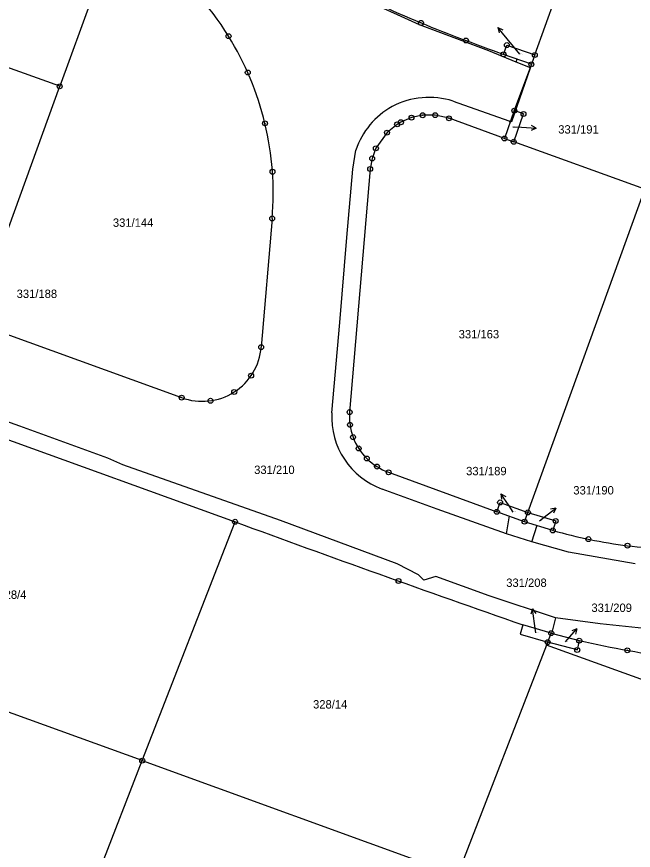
# Model space of a CAD drawing. Extents: x -770973 to -770265, y -1049936 to -1049427.
# Drawn here: x -770637.6 to -770575, y -1049731.9 to -1049647.3 of the extents above; entities that cross this region are included whole.
import ezdxf

# ---------------------------------------------------------------- set-up
doc = ezdxf.new("R2010")
doc.units = 0
for name, color, linetype in [('Vrstva 1', 7, 'Continuous'), ('Vrstva 13', 7, 'Continuous'), ('Vrstva 14', 7, 'Continuous'), ('Vrstva 16', 7, 'Continuous'), ('Vrstva 28', 7, 'Continuous'), ('Vrstva 50', 7, 'Continuous')]:
    doc.layers.add(name, color=color, linetype=linetype)

msp = doc.modelspace()

# ---------------------------------------------------------------- linework, layer by layer
at = {"layer": 'Vrstva 1'}
for p, q in [((-770584.98, -1049651.2), (-770577.41, -1049630.29)), ((-770627.29, -1049638.1), (-770633.21, -1049654.38)), ((-770633.21, -1049654.38), (-770663.4, -1049643.45)), ((-770588.15, -1049651.14), (-770587.82, -1049650.2)), ((-770587.82, -1049650.2), (-770584.98, -1049651.2)), ((-770585.33, -1049652.15), (-770588.15, -1049651.14)), ((-770584.98, -1049651.2), (-770585.33, -1049652.15)), ((-770585.33, -1049652.15), (-770587.06, -1049656.85)), ((-770641.55, -1049677.41), (-770633.21, -1049654.38)), ((-770587.06, -1049656.85), (-770588.06, -1049659.68)), ((-770587.12, -1049660.01), (-770586.12, -1049657.19)), ((-770586.12, -1049657.19), (-770587.06, -1049656.85)), ((-770598.57, -1049658.03), (-770598.96, -1049658.24)), ((-770597.5, -1049657.56), (-770598.57, -1049658.03)), ((-770596.36, -1049657.32), (-770597.5, -1049657.56)), ((-770595.1, -1049657.31), (-770596.36, -1049657.32)), ((-770593.69, -1049657.63), (-770595.1, -1049657.31)), ((-770588.06, -1049659.68), (-770593.69, -1049657.63)), ((-770598.96, -1049658.24), (-770599.98, -1049659.08)), ((-770599.98, -1049659.08), (-770601.11, -1049660.67)), ((-770588.06, -1049659.68), (-770587.12, -1049660.01)), ((-770601.11, -1049660.67), (-770601.49, -1049661.7)), ((-770573.81, -1049664.83), (-770587.12, -1049660.01)), ((-770601.49, -1049661.7), (-770601.69, -1049662.77)), ((-770601.69, -1049662.77), (-770603.78, -1049687.44)), ((-770585.68, -1049697.62), (-770573.81, -1049664.83)), ((-770611.64, -1049667.79), (-770612.76, -1049680.85)), ((-770639.05, -1049679.38), (-770620.83, -1049685.97)), ((-770644.61, -1049688), (-770615.41, -1049698.57)), ((-770599.82, -1049693.55), (-770588.83, -1049697.56)), ((-770588.83, -1049697.56), (-770588.5, -1049696.61)), ((-770588.5, -1049696.61), (-770585.68, -1049697.62)), ((-770586.02, -1049698.56), (-770588.83, -1049697.56)), ((-770586.02, -1049698.56), (-770585.68, -1049697.62)), ((-770585.68, -1049697.62), (-770582.86, -1049698.49)), ((-770624.83, -1049722.81), (-770615.41, -1049698.57)), ((-770583.15, -1049699.45), (-770586.02, -1049698.56)), ((-770582.86, -1049698.49), (-770583.15, -1049699.45)), ((-770586.18, -1049709.03), (-770586.46, -1049709.99)), ((-770583.31, -1049709.87), (-770586.18, -1049709.03)), ((-770586.46, -1049709.99), (-770583.67, -1049710.78)), ((-770583.67, -1049710.78), (-770583.31, -1049709.87)), ((-770583.31, -1049709.87), (-770580.47, -1049710.63)), ((-770624.83, -1049722.81), (-770656.82, -1049711.23)), ((-770583.79, -1049711.08), (-770592.84, -1049734.39)), ((-770583.79, -1049711.08), (-770583.67, -1049710.78)), ((-770552.69, -1049722.34), (-770583.79, -1049711.08)), ((-770580.67, -1049711.58), (-770583.67, -1049710.78)), ((-770580.47, -1049710.63), (-770580.67, -1049711.58)), ((-770633.88, -1049746.11), (-770624.83, -1049722.81)), ((-770624.83, -1049722.81), (-770592.84, -1049734.39))]:
    msp.add_line(p, q, dxfattribs=at)
for centre, radius, start, end in [((-770641.671, -1049665.124), 30.101, 31.7359, 52.91598), ((-770563.212, -1049566.923), 87.609, 241.27361, 247.64799), ((-770506.43, -1049423.863), 241.523, 248.09613, 250.22338), ((-770641.784, -1049665.239), 30.258, 13.56856, 31.809), ((-770641.923, -1049665.228), 30.391, 355.16466, 13.48744), ((-770618.706, -1049680.376), 5.965, 302.62625, 355.44623), ((-770618.732, -1049680.33), 6.018, 249.591, 302.59454), ((-770597.707, -1049687.897), 6.09, 175.69338, 199.99797), ((-770597.943, -1049687.977), 5.841, 200.05783, 225.59925), ((-770597.728, -1049687.803), 6.116, 225.2978, 249.99497), ((-770023.191, -1048089.712), 1714.394, 249.791394, 250.82895), ((-770568.602, -1049647.614), 53.839, 254.32281, 262.56352), ((-770568.043, -1049639.768), 61.693, 262.99237, 270.30037), ((-770552.252, -1049582.755), 130.951, 257.55595, 262.02506)]:
    msp.add_arc(centre, radius, start, end, dxfattribs=at)
at = {"layer": 'Vrstva 13'}
for p, q in [((-770586.5, -1049651.12), (-770587.77, -1049649.57)), ((-770587.21, -1049658.48), (-770586.34, -1049658.54)), ((-770587.16, -1049697.59), (-770587.58, -1049696.96)), ((-770584.51, -1049698.49), (-770584.03, -1049698.11)), ((-770584.88, -1049709.84), (-770585.01, -1049708.9)), ((-770581.86, -1049710.76), (-770581.68, -1049710.55))]:
    msp.add_line(p, q, dxfattribs=at)
at = {"layer": 'Vrstva 16'}
for p, q in [((-770587.77, -1049649.57), (-770588.72, -1049648.41)), ((-770588.72, -1049648.41), (-770588.6, -1049648.95)), ((-770588.72, -1049648.41), (-770588.21, -1049648.64)), ((-770586.34, -1049658.54), (-770584.84, -1049658.63)), ((-770584.84, -1049658.63), (-770585.36, -1049658.85)), ((-770584.84, -1049658.63), (-770585.33, -1049658.35)), ((-770587.58, -1049696.96), (-770588.42, -1049695.72)), ((-770588.42, -1049695.72), (-770588.35, -1049696.27)), ((-770588.42, -1049695.72), (-770587.93, -1049695.99)), ((-770584.03, -1049698.11), (-770582.85, -1049697.19)), ((-770582.85, -1049697.19), (-770583.4, -1049697.3)), ((-770582.85, -1049697.19), (-770583.09, -1049697.69)), ((-770585.21, -1049707.41), (-770585.39, -1049707.94)), ((-770585.01, -1049708.9), (-770585.21, -1049707.41)), ((-770585.21, -1049707.41), (-770584.89, -1049707.88)), ((-770581.68, -1049710.55), (-770580.7, -1049709.42)), ((-770580.7, -1049709.42), (-770581.21, -1049709.63)), ((-770580.7, -1049709.42), (-770580.84, -1049709.96))]:
    msp.add_line(p, q, dxfattribs=at)
at = {"layer": 'Vrstva 28'}
for centre, radius in [((-770596.53, -1049647.95), 0.25), ((-770596.53, -1049647.95), 0.005), ((-770616.07, -1049649.29), 0.25), ((-770616.07, -1049649.29), 0.005), ((-770591.97, -1049649.73), 0.25), ((-770591.97, -1049649.73), 0.005), ((-770587.82, -1049650.2), 0.25), ((-770587.82, -1049650.2), 0.005), ((-770588.15, -1049651.14), 0.25), ((-770588.15, -1049651.14), 0.005), ((-770584.98, -1049651.2), 0.25), ((-770584.98, -1049651.2), 0.005), ((-770585.33, -1049652.15), 0.25), ((-770585.33, -1049652.15), 0.005), ((-770614.12, -1049652.98), 0.25), ((-770614.12, -1049652.98), 0.005), ((-770633.21, -1049654.38), 0.25), ((-770633.21, -1049654.38), 0.005), ((-770596.36, -1049657.32), 0.25), ((-770595.1, -1049657.31), 0.25), ((-770587.06, -1049656.85), 0.25), ((-770587.06, -1049656.85), 0.005), ((-770586.12, -1049657.19), 0.25), ((-770586.12, -1049657.19), 0.005), ((-770612.37, -1049658.14), 0.25), ((-770612.37, -1049658.14), 0.005), ((-770598.96, -1049658.24), 0.25), ((-770598.57, -1049658.03), 0.25), ((-770598.57, -1049658.03), 0.005), ((-770597.5, -1049657.56), 0.25), ((-770597.5, -1049657.56), 0.005), ((-770596.36, -1049657.32), 0.005), ((-770595.1, -1049657.31), 0.005), ((-770593.69, -1049657.63), 0.25), ((-770593.69, -1049657.63), 0.005), ((-770599.98, -1049659.08), 0.25), ((-770598.96, -1049658.24), 0.005), ((-770599.98, -1049659.08), 0.005), ((-770588.06, -1049659.68), 0.25), ((-770588.06, -1049659.68), 0.005), ((-770587.12, -1049660.01), 0.25), ((-770601.11, -1049660.67), 0.25), ((-770601.11, -1049660.67), 0.005), ((-770587.12, -1049660.01), 0.005), ((-770601.49, -1049661.7), 0.25), ((-770601.49, -1049661.7), 0.005), ((-770611.61, -1049663.05), 0.25), ((-770611.61, -1049663.05), 0.005), ((-770601.69, -1049662.77), 0.25), ((-770601.69, -1049662.77), 0.005), ((-770611.64, -1049667.79), 0.25), ((-770611.64, -1049667.79), 0.005), ((-770612.76, -1049680.85), 0.25), ((-770612.76, -1049680.85), 0.005), ((-770613.78, -1049683.74), 0.25), ((-770613.78, -1049683.74), 0.005), ((-770615.49, -1049685.4), 0.25), ((-770620.83, -1049685.97), 0.25), ((-770620.83, -1049685.97), 0.005), ((-770617.9, -1049686.29), 0.25), ((-770615.49, -1049685.4), 0.005), ((-770617.9, -1049686.29), 0.005), ((-770603.78, -1049687.44), 0.25), ((-770603.78, -1049687.44), 0.005), ((-770603.74, -1049688.73), 0.25), ((-770603.74, -1049688.73), 0.005), ((-770603.43, -1049689.98), 0.25), ((-770603.43, -1049689.98), 0.005), ((-770602.86, -1049691.13), 0.25), ((-770602.86, -1049691.13), 0.005), ((-770602.03, -1049692.15), 0.25), ((-770602.03, -1049692.15), 0.005), ((-770601, -1049692.97), 0.25), ((-770601, -1049692.97), 0.005), ((-770599.82, -1049693.55), 0.25), ((-770599.82, -1049693.55), 0.005), ((-770588.5, -1049696.61), 0.25), ((-770588.5, -1049696.61), 0.005), ((-770588.83, -1049697.56), 0.25), ((-770588.83, -1049697.56), 0.005), ((-770585.68, -1049697.62), 0.25), ((-770585.68, -1049697.62), 0.005), ((-770615.41, -1049698.57), 0.25), ((-770615.41, -1049698.57), 0.005), ((-770586.02, -1049698.56), 0.25), ((-770586.02, -1049698.56), 0.005), ((-770582.86, -1049698.49), 0.25), ((-770582.86, -1049698.49), 0.005), ((-770583.15, -1049699.45), 0.25), ((-770583.15, -1049699.45), 0.005), ((-770579.54, -1049700.33), 0.25), ((-770579.54, -1049700.33), 0.005), ((-770575.57, -1049701), 0.25), ((-770575.57, -1049701), 0.005), ((-770598.82, -1049704.58), 0.25), ((-770598.82, -1049704.58), 0.005), ((-770583.31, -1049709.87), 0.25), ((-770583.67, -1049710.78), 0.25), ((-770583.31, -1049709.87), 0.005), ((-770580.47, -1049710.63), 0.25), ((-770583.67, -1049710.78), 0.005), ((-770580.67, -1049711.58), 0.25), ((-770580.47, -1049710.63), 0.005), ((-770575.59, -1049711.61), 0.25), ((-770580.67, -1049711.58), 0.005), ((-770575.59, -1049711.61), 0.005), ((-770624.83, -1049722.81), 0.25), ((-770624.83, -1049722.81), 0.005)]:
    msp.add_circle(centre, radius, dxfattribs=at)
at = {"layer": 'Vrstva 50'}
for p, q in [((-770596.69, -1049648.13), (-770601.84, -1049645.81)), ((-770589.65, -1049650.78), (-770596.69, -1049648.13)), ((-770586.88, -1049651.93), (-770589.65, -1049650.78)), ((-770586.88, -1049651.93), (-770586.77, -1049651.61)), ((-770585.4, -1049652.5), (-770586.88, -1049651.93)), ((-770587.31, -1049657.96), (-770585.4, -1049652.5)), ((-770593.27, -1049655.88), (-770587.62, -1049657.89)), ((-770587.62, -1049657.89), (-770587.48, -1049658.07)), ((-770587.62, -1049657.89), (-770587.31, -1049657.96)), ((-770603.46, -1049662.78), (-770603.14, -1049660.85)), ((-770604.05, -1049669.71), (-770603.46, -1049662.78)), ((-770604.78, -1049678.35), (-770604.05, -1049669.71)), ((-770605.59, -1049687.53), (-770604.78, -1049678.35)), ((-770637.26, -1049688.86), (-770644.63, -1049686.31)), ((-770628.31, -1049692.12), (-770637.26, -1049688.86)), ((-770626.79, -1049692.8), (-770628.31, -1049692.12)), ((-770610.79, -1049698.43), (-770626.79, -1049692.8)), ((-770594.88, -1049697.28), (-770600.49, -1049695.25)), ((-770587.84, -1049699.78), (-770594.88, -1049697.28)), ((-770598.94, -1049702.83), (-770610.79, -1049698.43)), ((-770587.84, -1049699.78), (-770587.55, -1049697.96)), ((-770585.29, -1049700.62), (-770584.74, -1049698.9)), ((-770585.29, -1049700.62), (-770587.84, -1049699.78)), ((-770581.57, -1049701.66), (-770585.29, -1049700.62)), ((-770574.78, -1049702.84), (-770581.57, -1049701.66)), ((-770596.79, -1049703.95), (-770598.94, -1049702.83)), ((-770596.24, -1049704.51), (-770596.79, -1049703.95)), ((-770595.03, -1049704.14), (-770596.24, -1049704.51)), ((-770589.6, -1049706.07), (-770595.03, -1049704.14)), ((-770582.89, -1049708.33), (-770589.6, -1049706.07)), ((-770582.89, -1049708.33), (-770583.25, -1049709.79)), ((-770578.34, -1049708.92), (-770582.89, -1049708.33)), ((-770573.85, -1049709.39), (-770578.34, -1049708.92))]:
    msp.add_line(p, q, dxfattribs=at)
for centre, radius, start, end in [((-770595.701, -1049663.565), 8.061, 72.4461, 117.87609), ((-770595.652, -1049663.349), 7.894, 118.924, 161.54158), ((-770597.801, -1049687.929), 7.799, 177.06892, 249.83032)]:
    msp.add_arc(centre, radius, start, end, dxfattribs=at)

# ---------------------------------------------------------------- texts
at = {"layer": 'Vrstva 14'}
for s, height, p in [('331/192', 0.05, (-770586.5, -1049651.12)), ('331/191', 0.05, (-770587.21, -1049658.48)), ('331/144', 0.85, (-770627.81, -1049668.64)), ('331/163', 0.85, (-770592.71, -1049679.96)), ('331/210', 0.85, (-770613.47, -1049693.72)), ('331/189', 0.05, (-770587.16, -1049697.59)), ('331/190', 0.05, (-770584.51, -1049698.49)), ('328/4', 0.85, (-770639.43, -1049706.39)), ('331/208', 0.05, (-770584.88, -1049709.84)), ('331/209', 0.05, (-770581.86, -1049710.76)), ('328/14', 0.85, (-770607.49, -1049717.52))]:
    msp.add_text(s, height=height, dxfattribs=at).set_placement(p)
at = {"layer": 'Vrstva 16'}
for s, p in [('331/191', (-770582.6, -1049659.18)), ('331/188', (-770637.58, -1049675.86)), ('331/189', (-770591.95, -1049693.85)), ('331/190', (-770581.07, -1049695.8)), ('331/208', (-770587.88, -1049705.18)), ('331/209', (-770579.23, -1049707.72))]:
    msp.add_text(s, height=0.85, dxfattribs=at).set_placement(p)

doc.saveas('drawing.dxf')
